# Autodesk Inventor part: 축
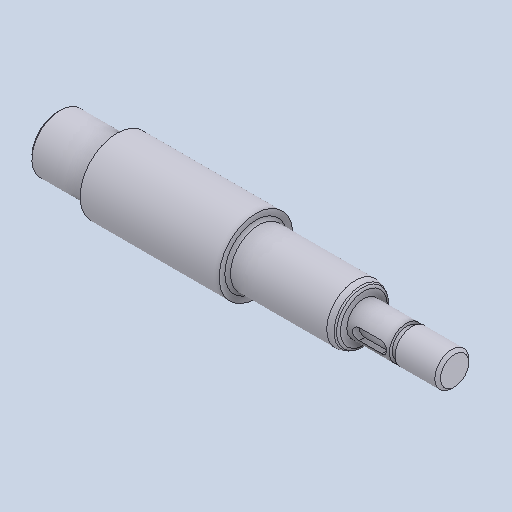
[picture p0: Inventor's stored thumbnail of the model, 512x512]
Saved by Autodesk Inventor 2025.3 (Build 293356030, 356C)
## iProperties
Created: 2025-08
Part Number: 축
Material: 강철, 연강
Document SubType Name: Modeling
Designer: user
Density: 7.86 g/cm^3
Appearance: 기본값
Author: jhkim
Sending System: Autodesk Inventor 2026
Preprocessor: ST-DEVELOPER v20.1
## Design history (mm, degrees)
sketch "스케치1"
  geometry: 1 further point
  constraints: 1 other
feature "솔리드2"
node "솔리드1"
